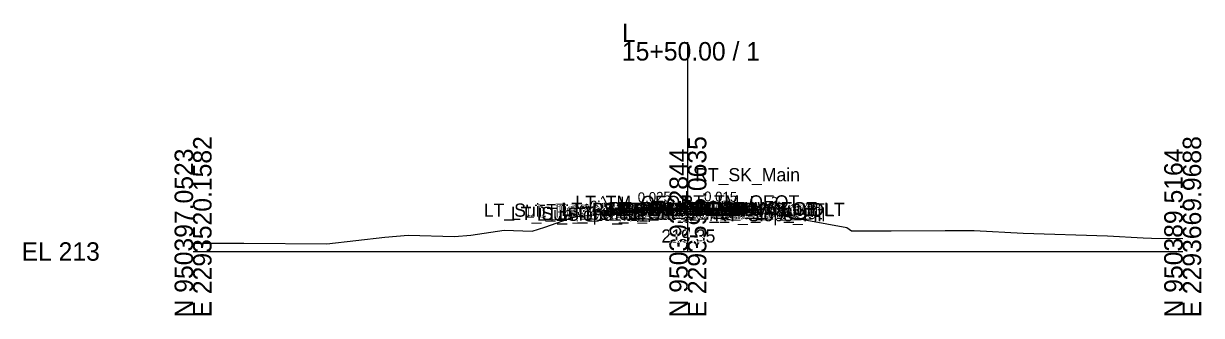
# Model space of a CAD drawing. Extents: x -26 to 7053, y -10 to 7035.
# Drawn here: x -25.7 to 152.8, y 6990.3 to 7034.6 of the extents above; entities that cross this region are included whole.
import ezdxf

# ---------------------------------------------------------------- set-up
doc = ezdxf.new("R2010")
doc.units = 0
for name, color, linetype in [('Default', 7, 'Continuous'), ('Exist Cross Section Cell', 7, 'Continuous'), ('Exist XS Center Line Elevation Label', 7, 'Continuous'), ('Exist XS Ground Line', 7, 'Continuous'), ('Prop CMT Pvmt Course 1', 7, 'Continuous'), ('Prop CMT Pvmt Course 2', 7, 'Continuous'), ('Prop CMT Pvmt Surface', 7, 'Continuous'), ('Prop CMT Pvmt Surface Overlay', 7, 'Continuous'), ('Prop CMT Pvmt Surface Shoulder', 7, 'Continuous'), ('Prop CMT Shld Paved Course 1', 7, 'Continuous'), ('Prop CMT Shld Paved Course 2', 7, 'Continuous'), ('Prop CMT Slope Grass', 7, 'Continuous'), ('Prop CMT Subgrade Earthwork', 7, 'Continuous'), ('Prop XS EOT Tick Mark', 7, 'Continuous'), ('Prop XS SE Text', 7, 'Continuous'), ('Prop XS Side Slope Text', 7, 'Continuous')]:
    doc.layers.add(name, color=color, linetype=linetype)

msp = doc.modelspace()

# ---------------------------------------------------------------- linework, layer by layer
at = {"layer": 'Exist Cross Section Cell'}
for p, q in [((75, 7000), (75, 7031.75)), ((0, 7000), (75, 7000)), ((75, 7000), (150, 7000))]:
    msp.add_line(p, q, dxfattribs=at)
at = {"layer": 'Exist XS Ground Line'}
for p, q in [((57.78, 7005.27), (65.93, 7006.09)), ((65.93, 7006.09), (72.37, 7006.28)), ((72.37, 7006.28), (74.61, 7006.36)), ((74.61, 7006.36), (75, 7006.35)), ((75, 7006.35), (82.04, 7006.15)), ((82.04, 7006.15), (83.28, 7006.1)), ((83.28, 7006.1), (84.94, 7005.96)), ((84.94, 7005.96), (87.83, 7005.72)), ((87.83, 7005.72), (93.03, 7004.77)), ((53.34, 7003.69), (57.78, 7005.27)), ((93.03, 7004.77), (99.07, 7003.63)), ((20.25, 7001.16), (29.05, 7002.16)), ((29.05, 7002.16), (32.6, 7002.46)), ((32.6, 7002.46), (39.64, 7002.28)), ((39.64, 7002.28), (42.12, 7002.48)), ((42.12, 7002.48), (47.17, 7003.24)), ((47.17, 7003.24), (49.97, 7003.15)), ((49.97, 7003.15), (51.38, 7003.07)), ((51.38, 7003.07), (53.34, 7003.69)), ((99.07, 7003.63), (99.79, 7003.12)), ((99.79, 7003.12), (105.83, 7003.12)), ((105.83, 7003.12), (114.01, 7003.16)), ((114.01, 7003.16), (118.4, 7003.17)), ((118.4, 7003.17), (125.81, 7002.79)), ((125.81, 7002.79), (138.59, 7002.36)), ((138.59, 7002.36), (144, 7002.06)), ((144, 7002.06), (145.29, 7002.02)), ((0, 7001.26), (2.39, 7001.28)), ((2.39, 7001.28), (7.67, 7001.26)), ((7.67, 7001.26), (20.25, 7001.16)), ((145.29, 7002.02), (150, 7001.98))]:
    msp.add_line(p, q, dxfattribs=at)
at = {"layer": 'Prop CMT Pvmt Course 1'}
for points in [[(75, 7006.64), (65.08, 7006.39)], [(65.08, 7006.39), (65.08, 7006.14)], [(65.08, 7006.14), (75, 7006.39)], [(75, 7006.51), (75, 7006.64)], [(75, 7006.64), (84.69, 7006.49)], [(75, 7006.51), (75, 7006.64)], [(75, 7006.39), (75, 7006.51), (75, 7006.51)], [(75, 7006.39), (75, 7006.51), (75, 7006.51)], [(84.69, 7006.24), (75, 7006.39)], [(84.69, 7006.49), (84.69, 7006.24)]]:
    msp.add_lwpolyline(points, dxfattribs=at)
at = {"layer": 'Prop CMT Pvmt Course 2'}
for points in [[(75, 7006.39), (65.08, 7006.14)], [(65.08, 7006.14), (65.08, 7005.81)], [(65.08, 7005.81), (75, 7006.05)], [(75, 7006.05), (75, 7006.39)], [(75, 7006.05), (75, 7006.39)], [(75, 7006.39), (84.69, 7006.24)], [(84.69, 7005.91), (75, 7006.05)], [(84.69, 7006.24), (84.69, 7005.91)]]:
    msp.add_lwpolyline(points, dxfattribs=at)
at = {"layer": 'Prop CMT Pvmt Surface'}
for points in [[(75, 7006.64), (65.08, 7006.39)], [(75, 7006.64), (84.69, 7006.49)]]:
    msp.add_lwpolyline(points, dxfattribs=at)
at = {"layer": 'Prop CMT Pvmt Surface Overlay'}
for points in [[(75, 7006.64), (65.08, 7006.39)], [(75, 7006.64), (84.69, 7006.49)]]:
    msp.add_lwpolyline(points, dxfattribs=at)
at = {"layer": 'Prop CMT Pvmt Surface Shoulder'}
for points in [[(65.08, 7006.39), (65.07, 7006.39)], [(84.69, 7006.49), (84.7, 7006.49)]]:
    msp.add_lwpolyline(points, dxfattribs=at)
at = {"layer": 'Prop CMT Shld Paved Course 1'}
for points in [[(65.08, 7006.39), (65.07, 7006.39), (64.82, 7006.14)], [(64.82, 7006.14), (65.08, 7006.14)], [(65.08, 7006.14), (65.08, 7006.39)], [(84.69, 7006.49), (84.7, 7006.49), (84.95, 7006.24)], [(84.69, 7006.24), (84.69, 7006.49)], [(84.95, 7006.24), (84.69, 7006.24)]]:
    msp.add_lwpolyline(points, dxfattribs=at)
at = {"layer": 'Prop CMT Shld Paved Course 2'}
for points in [[(65.08, 7006.14), (64.82, 7006.14), (64.32, 7006.12), (63.97, 7005.78)], [(63.97, 7005.78), (65.08, 7005.81)], [(65.08, 7005.81), (65.08, 7006.14)], [(84.69, 7006.24), (84.95, 7006.24), (85.45, 7006.23), (85.79, 7005.9)], [(84.69, 7005.91), (84.69, 7006.24)], [(85.79, 7005.9), (84.69, 7005.91)]]:
    msp.add_lwpolyline(points, dxfattribs=at)
at = {"layer": 'Prop CMT Slope Grass'}
for points in [[(62.68, 7006.2), (61.58, 7005.65)], [(65.07, 7006.39), (62.68, 7006.2)], [(84.7, 7006.49), (87.1, 7006.32)], [(87.1, 7006.32), (88.56, 7005.58)]]:
    msp.add_lwpolyline(points, dxfattribs=at)
at = {"layer": 'Prop CMT Subgrade Earthwork'}
for points in [[(63.97, 7005.78), (63.49, 7006.27)], [(65.08, 7005.81), (63.97, 7005.78)], [(75, 7006.05), (65.08, 7005.81)], [(75, 7006.05), (84.69, 7005.91)], [(84.69, 7005.91), (85.79, 7005.9)], [(85.79, 7005.9), (86.27, 7006.38)]]:
    msp.add_lwpolyline(points, dxfattribs=at)
at = {"layer": 'Prop XS EOT Tick Mark'}
for p, q in [((65.08, 7006.39), (65.08, 7008.3)), ((84.69, 7006.49), (84.69, 7008.4))]:
    msp.add_line(p, q, dxfattribs=at)

# ---------------------------------------------------------------- texts
at = {"layer": 'Default'}
for s, height, p in [('RT_SK_Main', 2, (76.09, 7010.64)), ('LT_PV1_OEOT', 2, (55.82, 7005.39)), ('LT_PS1_OEOP', 2, (55.88, 7005.39)), ('LT_TM_OEOT', 2, (57.94, 7006.44)), ('RT_PV1_OEEOP_W', 2, (62.94, 7005.51)), ('LT_PV1_OEEOP_W', 2, (62.98, 7005.51)), ('RT_PV2_OEEOP', 2, (64.26, 7005.39)), ('LT_PV2_OEEOP', 2, (64.31, 7005.39)), ('RT_Sub_Trench_Out_DLT', 2, (66.79, 7005.38)), ('PV1_PGL_W', 2, (67.58, 7005.51)), ('PV1_PGL', 2, (69.47, 7005.64)), ('RT_TM_OEOT', 2, (73.9, 7006.52)), ('RT_PV1_OEOT', 2, (75.38, 7005.49)), ('RT_PS1_OEOP', 2, (75.46, 7005.49)), ('LT_Sub_Trench_Out_DLT', 2, (44.06, 7005.27)), ('LT_Sub_Trench_Out', 2, (48.18, 7004.78)), ('LT_PS2_Shelf_Out', 2, (50.3, 7005.12)), ('LT_GS_OS_CTL', 2, (52.05, 7005.2)), ('LT_Slope_Fill', 2, (52.1, 7004.65)), ('LT_PS2_OEOP', 2, (55.05, 7005.14)), ('LT_Sub_OEOT', 2, (55.16, 7004.81)), ('LT_PV2_OEOT', 2, (55.26, 7005.14)), ('RT_Sub_OEEOP', 2, (64.17, 7005.05)), ('LT_Sub_OEEOP', 2, (64.21, 7005.05)), ('RT_Sub_Trench_Out', 2, (69.95, 7004.9)), ('RT_PS2_Shelf_Out', 2, (71.39, 7005.23)), ('RT_Sub_OEOT', 2, (74.72, 7004.91)), ('RT_PV2_OEOT', 2, (74.82, 7005.24)), ('RT_PS2_OEOP', 2, (75.14, 7005.24)), ('RT_GS_OS_CTL', 2, (76.42, 7005.32)), ('RT_Slope_Fill', 2, (79.03, 7004.58)), ('-', 0.0001, (0, 7000))]:
    msp.add_text(s, height=height, dxfattribs=at).set_placement(p)
at = {"layer": 'Exist Cross Section Cell'}
for s, p in [('L', (65, 7031.75)), ('15+50.00 / 1', (65, 7028.95)), ('EL 213', (-26, 6998.6))]:
    msp.add_text(s, height=2.8, dxfattribs=at).set_placement(p)
for s, p in [('E 2293520.1582', (2.8, 6990)), ('E 2293595.0635', (77.8, 6990)), ('E 2293669.9688', (152.8, 6990)), ('N 950397.0523', (0, 6990)), ('N 950393.2844', (75, 6990)), ('N 950389.5164', (150, 6990))]:
    msp.add_text(s, height=2.8, rotation=90, dxfattribs=at).set_placement(p)
at = {"layer": 'Exist XS Center Line Elevation Label'}
msp.add_text('219.35', height=2, dxfattribs=at).set_placement((70.98, 7001.35))
at = {"layer": 'Prop XS SE Text'}
for s, rotation, p in [('0.025', 1.4101, (67.42, 7007.45)), ('0.015', 359.1627, (77.44, 7007.6))]:
    msp.add_text(s, height=1.5, rotation=rotation, dxfattribs=at).set_placement(p)
at = {"layer": 'Prop XS Side Slope Text'}
for rotation, p in [(26.565, (60.73, 7006.06)), (333.4349, (87.1, 7007.15))]:
    msp.add_text('2:1', height=1.5, rotation=rotation, dxfattribs=at).set_placement(p)

doc.saveas('drawing.dxf')
